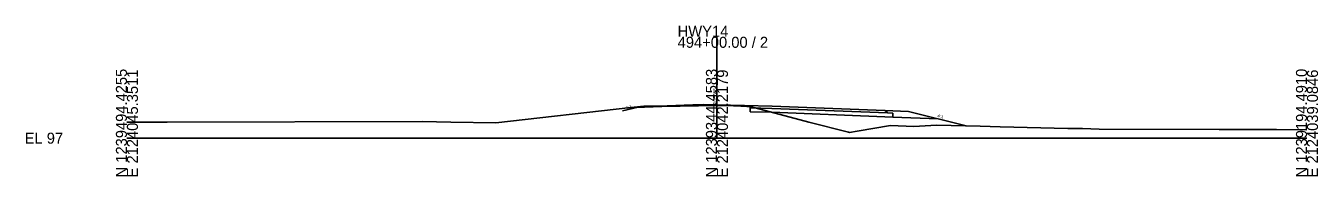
# Model space of a CAD drawing. Extents: x -26 to 303, y -10 to 11521.
# Drawn here: x -25.7 to 302.8, y 5490.3 to 5528.6 of the extents above; entities that cross this region are included whole.
import ezdxf

# ---------------------------------------------------------------- set-up
doc = ezdxf.new("R2010")
doc.units = 0
for name, color, linetype in [('XS_CELL', 7, 'Continuous'), ('XS_P_FINISHED_GRADE', 7, 'Continuous'), ('XS_P_SUBGRADE_GRANULAR', 7, 'Continuous'), ('XS_P_SUBGRADE_LEVELING', 7, 'Continuous'), ('XS_P_SUBGRADE_PAVEMENT', 7, 'Continuous'), ('XS_P_TX_FS_BS', 7, 'Continuous'), ('XS_X_GROUND', 7, 'Continuous'), ('XS_X_GROUND_TX', 7, 'Continuous')]:
    doc.layers.add(name, color=color, linetype=linetype)

msp = doc.modelspace()

# ---------------------------------------------------------------- linework, layer by layer
at = {"layer": 'XS_CELL'}
for p, q in [((150, 5500), (150, 5525.84)), ((0, 5500), (150, 5500)), ((150, 5500), (300, 5500))]:
    msp.add_line(p, q, dxfattribs=at)
at = {"layer": 'XS_P_FINISHED_GRADE'}
for p, q in [((130, 5507.94), (126, 5506.94)), ((136, 5508.18), (130, 5507.94)), ((150, 5508.46), (136, 5508.18)), ((150, 5508.46), (164, 5508.18)), ((164, 5508.18), (192.71, 5507.03)), ((192.71, 5507.03), (198.71, 5506.79)), ((198.71, 5506.79), (213.37, 5503.12))]:
    msp.add_line(p, q, dxfattribs=at)
at = {"layer": 'XS_P_SUBGRADE_GRANULAR'}
for p, q in [((136, 5508.05), (129.4, 5507.79)), ((158.44, 5506.7), (158.46, 5507.7)), ((158.44, 5506.7), (163.95, 5506.59)), ((163.95, 5506.59), (192.71, 5505.44)), ((193.34, 5506.42), (194.71, 5506.36)), ((194.71, 5505.36), (194.71, 5506.36)), ((192.71, 5505.44), (194.71, 5505.36)), ((194.71, 5505.36), (206.26, 5504.9))]:
    msp.add_line(p, q, dxfattribs=at)
at = {"layer": 'XS_P_SUBGRADE_LEVELING'}
for p, q in [((150, 5508.33), (136, 5508.05)), ((136, 5508.05), (136, 5508.18)), ((150, 5508.33), (158.46, 5508.16)), ((158.46, 5508.16), (158.46, 5508.29))]:
    msp.add_line(p, q, dxfattribs=at)
at = {"layer": 'XS_P_SUBGRADE_PAVEMENT'}
for p, q in [((158.46, 5507.7), (158.46, 5508.16)), ((158.46, 5507.7), (163.99, 5507.59)), ((163.98, 5507.59), (193.34, 5506.42)), ((192.71, 5507.03), (193.19, 5506.68)), ((192.71, 5507.03), (193.19, 5506.68)), ((193.19, 5506.68), (193.33, 5506.43)), ((193.19, 5506.68), (193.34, 5506.42))]:
    msp.add_line(p, q, dxfattribs=at)
at = {"layer": 'XS_X_GROUND'}
for p, q in [((93.82, 5503.91), (128.1, 5507.81)), ((128.1, 5507.81), (131.45, 5508.14)), ((131.45, 5508.14), (131.78, 5508.15)), ((131.78, 5508.15), (135.12, 5508.18)), ((135.12, 5508.18), (143.83, 5508.51)), ((143.83, 5508.51), (146.68, 5508.61)), ((146.68, 5508.61), (150, 5508.46)), ((150, 5508.46), (154.46, 5508.24)), ((154.46, 5508.24), (157.59, 5508.11)), ((157.59, 5508.11), (158.46, 5508.04)), ((158.46, 5508.04), (173.4, 5504.09)), ((0, 5504.09), (10.22, 5504.12)), ((10.22, 5504.12), (75.09, 5504.24)), ((75.09, 5504.24), (82.31, 5504.09)), ((82.31, 5504.09), (93.82, 5503.91)), ((173.4, 5504.09), (183.43, 5501.57)), ((185.68, 5501.82), (194.11, 5503.22)), ((194.11, 5503.22), (200.07, 5503.01)), ((200.07, 5503.01), (205.85, 5503.34)), ((205.85, 5503.34), (216.89, 5503.02)), ((216.89, 5503.02), (221.98, 5502.91)), ((183.43, 5501.57), (183.73, 5501.49)), ((183.73, 5501.49), (185.68, 5501.82)), ((221.98, 5502.91), (239.17, 5502.47)), ((239.17, 5502.47), (242.96, 5502.48)), ((242.96, 5502.48), (247.16, 5502.32)), ((247.16, 5502.32), (277.69, 5502.2)), ((277.69, 5502.2), (292.22, 5502.19)), ((292.22, 5502.19), (300, 5502.12))]:
    msp.add_line(p, q, dxfattribs=at)

# ---------------------------------------------------------------- texts
at = {"layer": 'XS_CELL'}
for s, p in [('494+00.00 / 2', (140, 5523.04)), ('HWY14', (140, 5525.84)), ('EL 97', (-26, 5498.6))]:
    msp.add_text(s, height=2.8, dxfattribs=at).set_placement(p)
for s, p in [('N 1239494.4255', (0, 5490)), ('E 2124045.3511', (2.8, 5490)), ('N 1239344.4583', (150, 5490)), ('E 2124042.2179', (152.8, 5490)), ('N 1239194.4910', (300, 5490)), ('E 2124039.0846', (302.8, 5490))]:
    msp.add_text(s, height=2.8, rotation=90, dxfattribs=at).set_placement(p)
at = {"layer": 'XS_P_TX_FS_BS'}
for rotation, p in [(14.0362, (126.88, 5507.33)), (345.9638, (205.98, 5505.38))]:
    msp.add_text('4:1', height=0.8, rotation=rotation, dxfattribs=at).set_placement(p)
at = {"layer": 'XS_X_GROUND_TX'}
msp.add_text('105.46', height=1, rotation=90, dxfattribs=at).set_placement((150, 5508.56))

doc.saveas('drawing.dxf')
